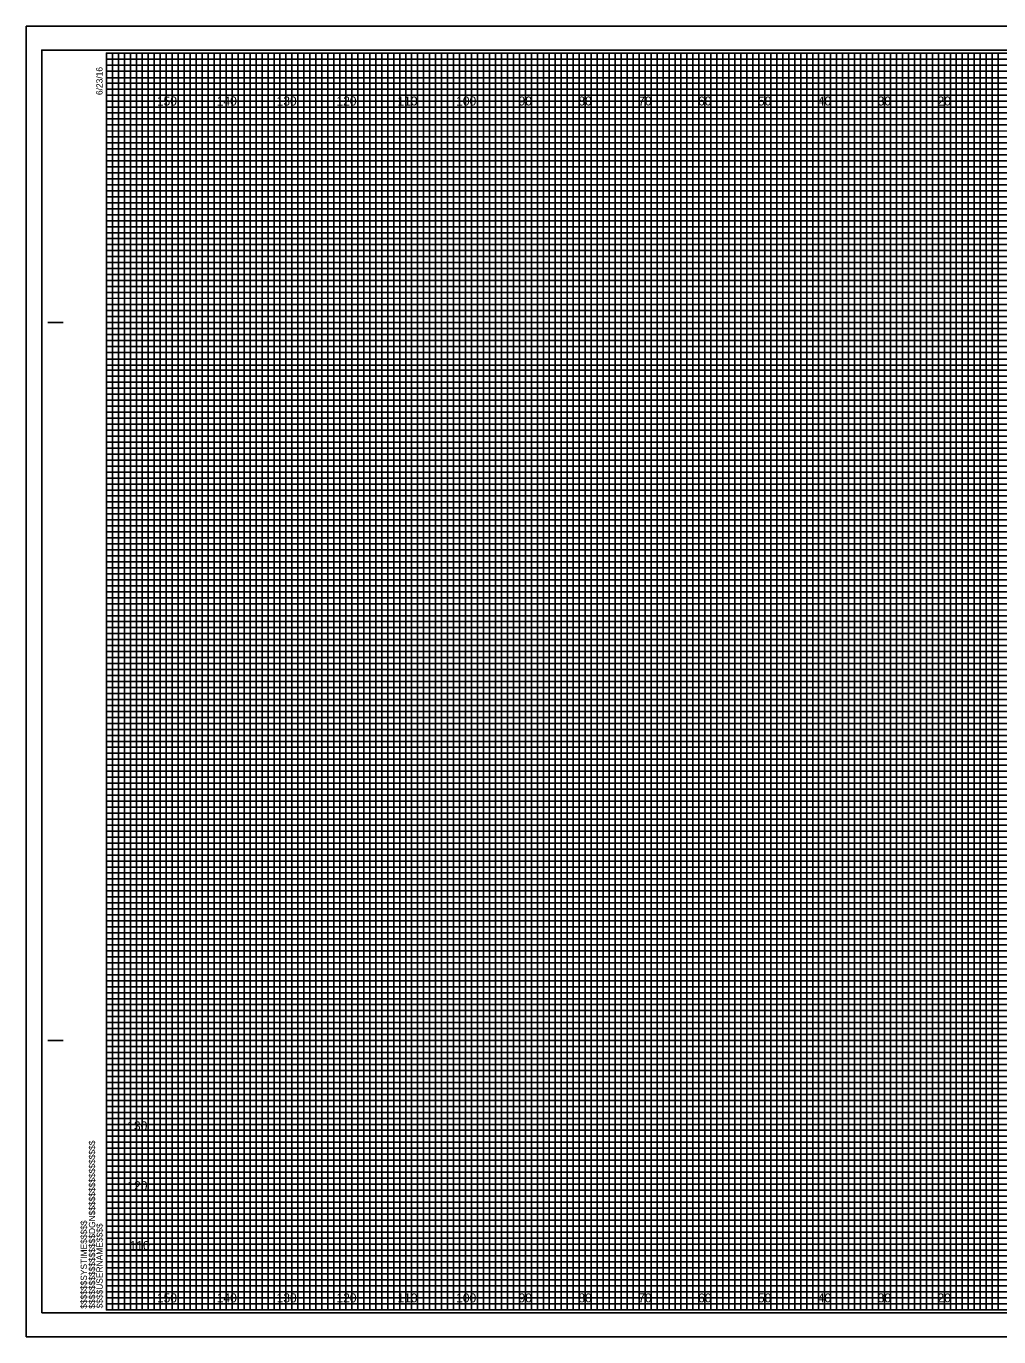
# Model space of a CAD drawing. Extents: x -13 to 323, y -5 to 434.
# Drawn here: x -13.4 to 149.1, y 215.5 to 434.5 of the extents above; entities that cross this region are included whole.
import ezdxf

# ---------------------------------------------------------------- set-up
doc = ezdxf.new("R2010")
doc.units = 0
for name, color, linetype in [('Prop XS Elevation Labels', 7, 'Continuous'), ('Prop XS Offset Labels', 7, 'Continuous'), ('Sheet Cross Section CELL', 7, 'Continuous'), ('Sheet Cross Section Grid Major CELL', 7, 'Continuous'), ('Sheet Cross Section Grid Middle CELL', 7, 'Continuous'), ('Sheet Cross Section Grid Minor 1 CELL', 7, 'Continuous'), ('Sheet Cross Section Grid Minor 2 CELL', 7, 'Continuous'), ('Sheet Cutting Line CELL', 7, 'Continuous'), ('Sheet DOT Grid CELL', 7, 'Continuous'), ('Sheet Plot Border Inside CELL', 7, 'Continuous'), ('Sheet Plot Border Outside CELL', 7, 'Continuous')]:
    doc.layers.add(name, color=color, linetype=linetype)

msp = doc.modelspace()

# ---------------------------------------------------------------- linework, layer by layer
at = {"layer": 'Sheet Cross Section CELL'}
for p, q in [((-9.8, 385), (-7.3, 385)), ((-9.7, 385), (-7.2, 385)), ((-9.8, 265), (-7.3, 265)), ((-9.7, 265), (-7.2, 265)), ((0, 220), (0, 220)), ((0, 220), (0, 220)), ((0, 220), (0, 220)), ((0, 220), (0, 220)), ((0, 220), (0, 220)), ((0, 220), (0, 220)), ((0, 220), (0, 220))]:
    msp.add_line(p, q, dxfattribs=at)
msp.add_lwpolyline([(320, 430), (0, 430), (0, 220), (320, 220)], close=True, dxfattribs=at)
at = {"layer": 'Sheet Cross Section Grid Major CELL'}
for p, q in [((10, 430), (0, 430)), ((10, 220), (10, 430)), ((30, 430), (20, 430)), ((20, 430), (20, 220)), ((30, 220), (30, 430)), ((50, 430), (40, 430)), ((40, 430), (40, 220)), ((50, 220), (50, 430)), ((70, 430), (60, 430)), ((60, 430), (60, 220)), ((70, 220), (70, 430)), ((90, 430), (80, 430)), ((80, 430), (80, 220)), ((90, 220), (90, 430)), ((110, 430), (100, 430)), ((100, 430), (100, 220)), ((110, 220), (110, 430)), ((130, 430), (120, 430)), ((120, 430), (120, 220)), ((130, 220), (130, 430)), ((150, 430), (140, 430)), ((140, 430), (140, 220)), ((20, 220), (10, 220)), ((40, 220), (30, 220)), ((60, 220), (50, 220)), ((80, 220), (70, 220)), ((100, 220), (90, 220)), ((120, 220), (110, 220)), ((140, 220), (130, 220))]:
    msp.add_line(p, q, dxfattribs=at)
for points in [[(0, 420), (320, 420), (320, 410), (0, 410)], [(0, 400), (320, 400), (320, 390), (0, 390)], [(0, 380), (320, 380), (320, 370), (0, 370)], [(0, 360), (320, 360), (320, 350), (0, 350)], [(0, 340), (320, 340), (320, 330), (0, 330)], [(0, 320), (320, 320), (320, 310), (0, 310)], [(0, 300), (320, 300), (320, 290), (0, 290)], [(0, 280), (320, 280), (320, 270), (0, 270)], [(0, 260), (320, 260), (320, 250), (0, 250)], [(0, 240), (320, 240), (320, 230), (0, 230)]]:
    msp.add_lwpolyline(points, dxfattribs=at)
at = {"layer": 'Sheet Cross Section Grid Middle CELL'}
for points in [[(0, 430), (5, 430), (5, 220), (15, 220), (15, 430), (25, 430), (25, 220), (35, 220), (35, 430), (45, 430), (45, 220), (55, 220), (55, 430), (65, 430), (65, 220), (75, 220), (75, 430), (85, 430), (85, 220), (95, 220), (95, 430), (105, 430), (105, 220), (115, 220), (115, 430), (125, 430), (125, 220), (135, 220), (135, 430), (145, 430), (145, 220), (155, 220)], [(0, 425), (275, 425)], [(0, 405), (320, 405), (320, 415), (0, 415)], [(0, 385), (320, 385), (320, 395), (0, 395)], [(0, 365), (320, 365), (320, 375), (0, 375)], [(0, 345), (320, 345), (320, 355), (0, 355)], [(0, 325), (320, 325), (320, 335), (0, 335)], [(0, 305), (320, 305), (320, 315), (0, 315)], [(0, 285), (320, 285), (320, 295), (0, 295)], [(0, 265), (320, 265), (320, 275), (0, 275)], [(0, 245), (320, 245), (320, 255), (0, 255)], [(0, 225), (320, 225), (320, 235), (0, 235)]]:
    msp.add_lwpolyline(points, dxfattribs=at)
at = {"layer": 'Sheet Cross Section Grid Minor 1 CELL'}
for p, q in [((0, 429), (260, 429)), ((260, 427.98), (0, 427.98)), ((0, 427.98), (0, 427)), ((0, 427), (260, 427)), ((260, 425.89), (0, 425.89)), ((0, 425.89), (0, 424)), ((0, 424), (320, 424))]:
    msp.add_line(p, q, dxfattribs=at)
for points in [[(0, 423), (270, 423), (320, 423), (320, 422), (0, 422)], [(0, 421), (320, 421), (320, 419), (0, 419)], [(0, 418), (320, 418), (320, 417), (0, 416.98)], [(0, 416), (320, 416), (320, 414), (0, 414)], [(0, 413), (320, 413), (320, 412), (0, 412)], [(0, 411), (320, 411), (320, 409), (0, 409)], [(0, 408), (320, 408), (320, 407), (0, 407)], [(0, 406), (320, 406), (320, 404), (0, 404)], [(0, 403), (320, 403), (320, 402), (0, 402)], [(0, 401), (320, 401), (320, 399), (0, 399)], [(0, 398), (320, 398), (320, 397), (0, 397)], [(0, 396), (320, 396), (320, 393.95), (320, 393), (320, 392), (0, 392)], [(0, 394), (320, 394), (320, 393), (0, 393)], [(0, 391), (320, 391), (320, 389), (0, 389.03)], [(0, 389.03), (320, 389), (320, 388), (0, 388)], [(0, 387), (320, 387), (320, 386), (0, 386)], [(0, 384), (320, 384), (320, 383), (0, 383)], [(0, 382), (320, 382), (320, 381), (0, 381)], [(-0.07, 378.89), (320, 378.89), (320, 377.88), (-0.07, 377.88)], [(0, 377), (320, 377), (320, 376), (0, 376)], [(0, 374), (320, 374), (320, 373), (0, 373)], [(0, 372), (320, 372), (320, 371), (0, 371)], [(0, 369), (320, 369), (320, 368), (0, 368)], [(0, 367), (320, 367), (320, 366), (0, 366)], [(0, 364), (320, 364), (320, 363), (0, 363)], [(0, 362), (320, 362), (320, 361), (0, 361)], [(0, 359), (320, 359), (319.99, 357.98), (0, 358)], [(0, 357), (320, 357), (320, 356), (0, 356)], [(0, 354), (320, 354), (320, 353), (0, 353)], [(0, 352), (320, 352), (320, 351), (0, 351)], [(0, 349), (320, 349), (320, 348), (0, 348)], [(0, 347), (320, 347), (320, 346), (0, 346)], [(0, 344), (320, 344), (320, 343), (0, 343)], [(0, 342), (320, 342), (320, 341), (0, 341)], [(0, 339), (320, 339), (320, 338), (0, 338)], [(0, 336.99), (320.07, 336.91), (320, 336), (0, 336)], [(0, 334), (320, 334), (320, 333), (0, 333)], [(0, 332), (320, 332), (320, 331), (0, 331)], [(0, 329), (320, 329), (320, 328), (0, 328)], [(0, 327), (320, 327), (320, 326), (0, 326)], [(0, 324), (320, 324), (320, 323), (0, 323)], [(0, 322), (320, 322), (320, 321), (0, 321)], [(0, 319), (320, 319), (320, 318), (0, 318)], [(0, 317), (320, 317), (320, 316), (0, 316)], [(0, 314), (320, 314), (320, 313), (0, 313)], [(0, 312), (320, 312), (320, 311), (0, 311)], [(0, 309), (320, 309), (320, 308), (0, 308)], [(0, 307), (320, 307), (320, 306), (0, 306)], [(0, 304), (320, 304), (320, 303), (0, 303)], [(0, 302), (320, 302), (320, 301), (0, 301)], [(0, 299), (320, 299), (319.99, 297.98), (0, 298)], [(0, 297), (320, 297), (320, 296), (0, 296)], [(0, 294), (320, 294), (320, 293), (0, 293)], [(0, 292), (320, 292), (320, 291), (0, 291)], [(0, 289), (320, 289), (320, 288), (0, 288)], [(0, 287), (320, 287), (320, 286), (0, 286)], [(0, 284), (320, 284), (320, 283), (0, 283)], [(0, 282), (320, 282), (320, 281), (0, 281)], [(0, 279), (320, 279), (320, 278), (0, 278)], [(0, 276.99), (320.07, 276.91), (320, 276), (0, 276)], [(0, 274), (320, 274), (320, 273), (0, 273)], [(0, 272), (320, 272), (320, 271), (0, 271)], [(0, 269), (320, 269), (320, 268), (0, 268)], [(0, 267), (320, 267), (320, 266), (0, 266)], [(0, 264), (320, 264), (320, 263), (0, 263)], [(0, 262), (320, 262), (320, 261), (0, 261)], [(0, 259), (320, 259), (320, 258), (0, 258)], [(0, 257), (320, 257), (320, 256), (0, 256)], [(0, 254), (320, 254), (320, 253), (0, 253)], [(0, 252), (320, 252), (320, 251), (0, 251)], [(0, 249), (320, 249), (320, 248), (0, 248)], [(0, 247), (320, 247), (320, 246), (0, 246)], [(0, 244), (320, 244), (320, 243), (0, 243)], [(0, 242), (320, 242), (320, 241), (0, 241)], [(0, 239), (320, 239), (320, 238), (0, 238)], [(0, 237), (320, 237), (320, 236), (0, 236)], [(0, 234), (320, 234), (320, 233), (0, 233)], [(0, 232), (320, 232), (320, 231), (0, 231)], [(0, 229), (320, 229), (320, 228), (0, 228)], [(0, 227), (320, 227), (320, 226), (0, 226)], [(0, 224), (320, 224), (320, 223), (0, 223)], [(0, 222), (320, 222), (320, 221), (0, 221)]]:
    msp.add_lwpolyline(points, dxfattribs=at)
at = {"layer": 'Sheet Cross Section Grid Minor 2 CELL'}
for points in [[(0, 220), (1, 220), (1, 430), (2, 430), (2, 220)], [(2, 220), (3, 220), (3, 430), (4, 430), (4, 220)], [(5, 220), (6, 220), (6, 430), (7, 430), (7, 220)], [(7, 220), (8, 220), (8, 430), (9, 430), (9, 220)], [(10, 220), (11, 220), (11, 430), (12, 430), (12, 220)], [(12, 220), (13, 220), (13, 430), (14, 430), (14, 220)], [(15, 220), (16, 220), (16, 430), (17, 430), (17, 220)], [(17, 220), (18, 220), (18, 430), (19, 430), (19, 220)], [(20, 220), (21, 220), (21, 430), (22, 430), (22, 220)], [(22, 220), (23, 220), (23, 430), (24, 430), (24, 220)], [(25, 220), (26, 220), (26, 430), (27, 430), (27, 220)], [(27, 220), (28, 220), (28, 430), (29, 430), (29, 220)], [(30, 220), (31, 220), (31, 430), (32, 430), (32, 220)], [(32, 220), (33, 220), (33, 430), (34, 430), (34, 220)], [(35, 220), (36, 220), (36, 430), (37, 430), (37, 220)], [(37, 220), (38, 220), (38, 430), (39, 430), (39, 220)], [(40, 220), (41, 220), (41, 430), (42, 430), (42, 220)], [(42, 220), (43, 220), (43, 430), (44, 430), (44, 220)], [(45, 220), (46, 220), (46, 430), (47, 430), (47, 220)], [(47, 220), (48, 220), (48, 430), (49, 430), (49, 220)], [(50, 220), (51, 220), (51, 430), (52, 430), (52, 220)], [(52, 220), (53, 220), (53, 430), (54, 430), (54, 220)], [(55, 220), (56, 220), (56, 430), (57, 430), (57, 220)], [(57, 220), (58, 220), (58, 430), (59, 430), (59, 220)], [(60, 220), (61, 220), (61, 430), (62, 430), (62, 220)], [(62, 220), (63, 220), (63, 430), (64, 430), (64, 220)], [(65, 220), (66, 220), (66, 430), (67, 430), (67, 220)], [(67, 220), (68, 220), (68, 430), (69, 430), (69, 220)], [(70, 220), (71, 220), (71, 430), (72, 430), (72, 220)], [(72, 220), (73, 220), (73, 430), (74, 430), (74, 220)], [(75, 220), (76, 220), (76, 430), (77, 430), (77, 220)], [(77, 220), (78, 220), (78, 430), (79, 430), (79, 220)], [(80, 220), (81, 220), (81, 430), (82, 430), (82, 220)], [(82, 220), (83, 220), (83, 430), (84, 430), (84, 220)], [(85, 220), (86, 220), (86, 430), (87, 430), (87, 220)], [(87, 220), (88, 220), (88, 430), (89, 430), (89, 220)], [(90, 220), (91, 220), (91, 430), (92, 430), (92, 220)], [(92, 220), (93, 220), (93, 430), (94, 430), (94, 220)], [(95, 220), (96, 220), (96, 430), (97, 430), (97, 220)], [(97, 220), (98, 220), (98, 430), (99, 430), (99, 220)], [(100, 220), (101, 220), (101, 430), (102, 430), (102, 220)], [(102, 220), (103, 220), (103, 430), (104, 430), (104, 220)], [(105, 220), (106, 220), (106, 430), (107, 430), (107, 220)], [(107, 220), (108, 220), (108, 430), (109, 430), (109, 220)], [(110, 220), (111, 220), (111, 430), (112, 430), (112, 220)], [(112, 220), (113, 220), (113, 430), (114, 430), (114, 220)], [(115, 220), (116, 220), (116, 430), (117, 430), (117, 220)], [(117, 220), (118, 220), (118, 430), (119, 430), (119, 220)], [(120, 220), (121, 220), (121, 430), (122, 430), (122, 220)], [(122, 220), (123, 220), (123, 430), (124, 430), (124, 220)], [(125, 220), (126, 220), (126, 430), (127, 430), (127, 220)], [(127, 220), (128, 220), (128, 430), (129, 430), (129, 220)], [(130, 220), (131, 220), (131, 430), (132, 430), (132, 220)], [(132, 220), (133, 220), (133, 430), (134, 430), (134, 220)], [(135, 220), (136, 220), (136, 430), (137, 430), (137, 220)], [(137, 220), (138, 220), (138, 430), (139, 430), (139, 220)], [(140, 220), (141, 220), (141, 430), (142, 430), (142, 220)], [(142, 220), (143, 220), (143, 430), (144, 430), (144, 220)], [(145, 220), (146, 220), (146, 430), (147, 430), (147, 220)], [(147, 220), (148, 220), (148, 430), (149, 430), (149, 220)]]:
    msp.add_lwpolyline(points, dxfattribs=at)
at = {"layer": 'Sheet Cutting Line CELL'}
for p, q in [((323.3, 434.5), (-13.4, 434.5)), ((-13.4, 434.5), (-13.4, 215.5)), ((-13.4, 215.5), (323.3, 215.5))]:
    msp.add_line(p, q, dxfattribs=at)
at = {"layer": 'Sheet DOT Grid CELL'}
for p, q in [((10, 220), (10, 430)), ((20, 220), (20, 430)), ((30, 220), (30, 430)), ((40, 220), (40, 430)), ((50, 220), (50, 430)), ((60, 220), (60, 430)), ((70, 220), (70, 430)), ((80, 220), (80, 430)), ((90, 220), (90, 430)), ((100, 220), (100, 430)), ((110, 220), (110, 430)), ((120, 220), (120, 430)), ((130, 220), (130, 430)), ((140, 220), (140, 430)), ((0, 420), (320, 420)), ((0, 410), (320, 410)), ((0, 400), (320, 400)), ((0, 390), (320, 390)), ((0, 380), (320, 380)), ((0, 370), (320, 370)), ((0, 360), (320, 360)), ((0, 350), (320, 350)), ((0, 340), (320, 340)), ((0, 330), (320, 330)), ((0, 320), (320, 320)), ((0, 310), (320, 310)), ((0, 300), (320, 300)), ((0, 290), (320, 290)), ((0, 280), (320, 280)), ((0, 270), (320, 270)), ((0, 260), (320, 260)), ((0, 250), (320, 250)), ((0, 240), (320, 240)), ((0, 230), (320, 230))]:
    msp.add_line(p, q, dxfattribs=at)
at = {"layer": 'Sheet Plot Border Inside CELL'}
msp.add_lwpolyline([(-10.8, 219.5), (322.4, 219.5), (322.4, 430.5), (-10.8, 430.5)], close=True, dxfattribs=at)
at = {"layer": 'Sheet Plot Border Outside CELL'}
msp.add_lwpolyline([(-13.4, 215.5), (323.3, 215.5), (323.3, 434.5), (-13.4, 434.5)], close=True, dxfattribs=at)

# ---------------------------------------------------------------- texts
at = {"layer": 'Prop XS Elevation Labels'}
for s, p in [('130', (3.49, 250)), ('120', (3.5, 240)), ('110', (3.88, 230))]:
    msp.add_text(s, height=1.5, dxfattribs=at).set_placement(p)
at = {"layer": 'Prop XS Offset Labels'}
for s, p in [('150', (8.44, 421.25)), ('140', (18.44, 421.25)), ('130', (28.44, 421.25)), ('120', (38.44, 421.25)), ('110', (48.62, 421.25)), ('100', (58.44, 421.25)), ('90', (68.86, 421.25)), ('80', (78.86, 421.25)), ('70', (88.86, 421.25)), ('60', (98.86, 421.25)), ('50', (108.86, 421.25)), ('40', (118.86, 421.25)), ('30', (128.86, 421.25)), ('20', (138.86, 421.25)), ('150', (8.44, 221.25)), ('140', (18.44, 221.25)), ('130', (28.44, 221.25)), ('120', (38.44, 221.25)), ('110', (48.62, 221.25)), ('100', (58.44, 221.25)), ('90', (68.86, 221.25)), ('80', (78.86, 221.25)), ('70', (88.86, 221.25)), ('60', (98.86, 221.25)), ('50', (108.86, 221.25)), ('40', (118.86, 221.25)), ('30', (128.86, 221.25)), ('20', (138.86, 221.25))]:
    msp.add_text(s, height=1.5, dxfattribs=at).set_placement(p)
at = {"layer": 'Sheet Cross Section CELL'}
for s, p in [('6/23/16', (-0.65, 423)), ('$$$$$$$$$$$$$$$$DGN$$$$$$$$$$$$$$$$', (-1.88, 220.18)), ('$$$$$$SYSTIME$$$$$', (-3.26, 220.18)), ('$$$$USERNAME$$$$', (-0.62, 220.23))]:
    msp.add_text(s, height=1.05, rotation=90, dxfattribs=at).set_placement(p)

doc.saveas('drawing.dxf')
